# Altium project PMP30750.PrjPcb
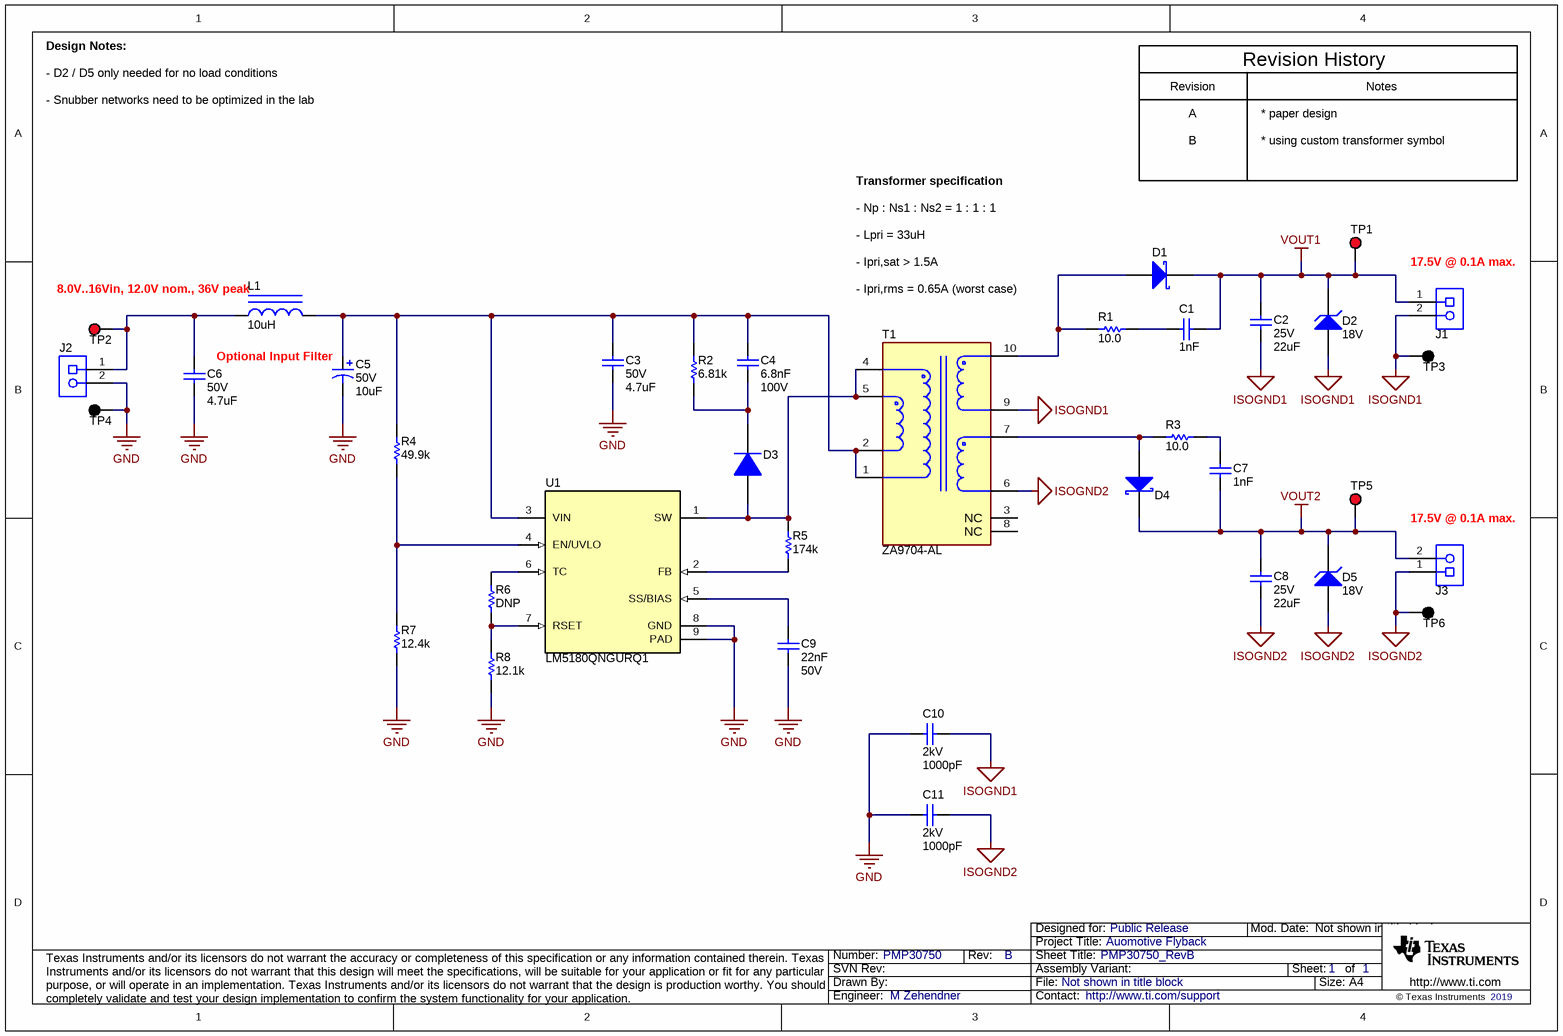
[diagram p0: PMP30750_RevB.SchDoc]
CopyrightYear: 2019; PCB_Rev: A; PRJ_Customer: Public Release; PRJ_Engineer: M Zehendner; PRJ_Number: PMP30750; PRJ_Title: Auomotive Flyback; SCH_Rev: B; TechSupport: http://www.ti.com/support; TID: N/A
1 sheet, 36 parts. Net scope: global (net labels, ports and power ports of the same name join across sheets).
Board file: PMP30750.PcbDoc

## Sheet PMP30750_RevB.SchDoc: PMP30750_RevB
size A4; Date: Not shown in title block; ApprovedBy: Not shown in title block; CheckedBy: Not shown in title block; Author: Not shown in title block; CompanyName: Not shown in title block; Engineer: Not shown in title block; Organization: Not shown in title block; Address1: Not shown in title block; Address2: Not shown in title block; Address3: Not shown in title block; Address4: Not shown in title block; DocumentNumber: 1; Revision: Use project parameter SCH_Rev; SheetNumber: 1; SheetTotal: 1; PageSetup: Record=PageOptions¦CenterHorizontal=True¦CenterVertical=True¦PrintScale=0.70¦XCorrection=1.00¦YCorrection=1.00¦PrintKind=0¦BorderSize=5000000¦LeftOffset=0¦BottomOffset=0¦Orientation=2¦PaperLength=1000¦PaperWidth=1000¦Scale=100¦PaperSource=15¦PrintQuality=600¦MediaType=1¦DitherType=10¦PaperKind=A4¦PrintScaleMode=1

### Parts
C1  Cap_F: 1nF  [0603]  (hidden comment: GRM188R71H102KA01D)
C2  VDC_V: 25V  ValueDisplayed: 22uF  [1210_270]  (hidden comment: TMK325B7226MM-PR)
C3  VDC_V: 50V  ValueDisplayed: 4.7uF  [1206_180]  (hidden comment: GRM31CR71H475KA12L)
C4  Cap_F: 6.8nF  VDC_V: 100V  [0603]  (hidden comment: GRM188R72A682KA01D)
C5  VDC_V: 50V  ValueDisplayed: 10uF  [SM_RADIAL_D]  (hidden comment: EEE-FK1H100P)
C6  VDC_V: 50V  ValueDisplayed: 4.7uF  [1206_180]  (hidden comment: GRM31CR71H475KA12L)
C7  Cap_F: 1nF  [0603]  (hidden comment: GRM188R71H102KA01D)
C8  VDC_V: 25V  ValueDisplayed: 22uF  [1210_270]  (hidden comment: TMK325B7226MM-PR)
C9  Cap_F: 22nF  VDC_V: 50V  [0603]  (hidden comment: GRM188R71H223KA01D)
C10  VDC_V: 2kV  ValueDisplayed: 1000pF  [1206_180]  (hidden comment: C1206C102KGRACAUTO)
C11  VDC_V: 2kV  ValueDisplayed: 1000pF  [1206_180]  (hidden comment: C1206C102KGRACAUTO)
D1  PMEG6010CEH,115  [SOD-123F]  (value not drawn)
D2  value 18V  [SOD-123]  (hidden comment: MMSZ5248B-7-F)
D3  BAS16D-E3-08  [SOD-123]  (value not drawn)
D4  PMEG6010CEH,115  [SOD-123F]  (value not drawn)
D5  value 18V  [SOD-123]  (hidden comment: MMSZ5248B-7-F)
J1  ED120/2DS  [On-Shore_ED120_2DS]  (value not drawn)
J2  ED120/2DS  [On-Shore_ED120_2DS]  (value not drawn)
J3  ED120/2DS  [On-Shore_ED120_2DS]  (value not drawn)
L1  ValueDisplayed: 10uH  [IHLP-2525CZ]  (hidden comment: IHLP2525CZER100M5A)
R1  ValueDisplayed: 10.0  [0603]  (hidden comment: CRCW060310R0FKEAHP)
R2  ValueDisplayed: 6.81k  [0603]  (hidden comment: CRCW06036K81FKEA)
R3  ValueDisplayed: 10.0  [0603]  (hidden comment: CRCW060310R0FKEAHP)
R4  ValueDisplayed: 49.9k  [0603]  (hidden comment: CRCW060349K9FKEA)
R5  ValueDisplayed: 174k  [0603]  (hidden comment: CRCW0603174KFKEA)
R6  ValueDisplayed: DNP  [0603]  (hidden comment: CRCW0603432KFKEA)
R7  ValueDisplayed: 12.4k  [0603]  (hidden comment: CRCW060312K4FKEA)
R8  ValueDisplayed: 12.1k  [0603]  (hidden comment: CRCW060312K1FKEA)
T1  ZA9704-AL  [FP-ZA9704-AL_SMD10-MFG]
TP1  5010  [Keystone5010]  (value not drawn)
TP2  5010  [Keystone5010]  (value not drawn)
TP3  5011  [Keystone5011]  (value not drawn)
TP4  5011  [Keystone5011]  (value not drawn)
TP5  5010  [Keystone5010]  (value not drawn)
TP6  5011  [Keystone5011]  (value not drawn)
U1  LM5180QNGURQ1  [NGU0008C]

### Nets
GND: C3.2 C5.2(-) C6.2 C9.2 C10.2 C11.2 J2.2 R7.1 R8.1 TP4.1 U1.8(GND) U1.9(PAD)
ISOGND1: C2.2 C10.1 D2.2(A) J1.2 T1.9 TP3.1
ISOGND2: C8.2 C11.1 D5.2(A) J3.1 T1.6 TP6.1
VOUT1: C1.1 C2.1 D1.1(K) D2.1(K) J1.1 TP1.1
VOUT2: C7.2 C8.1 D4.1(K) D5.1(K) J3.2 TP5.1
NetC1_2: C1.2 R1.2
NetC3_1: C3.1 C4.1 C5.1(+) L1.2 R2.2 R4.2 T1.1 T1.2 U1.3(VIN)
NetC4_2: C4.2 D3.1(K) R2.1
NetC6_1: C6.1 J2.1 L1.1 TP2.1
NetC7_1: C7.1 R3.2
NetC9_1: C9.1 U1.5(SS/BIAS)
NetD1_2: D1.2(A) R1.1 T1.10
NetD3_2: D3.2(A) R5.2 T1.4 T1.5 U1.1(SW)
NetD4_2: D4.2(A) R3.1 T1.7
NetR4_1: R4.1 R7.2 U1.4(EN/UVLO)
NetR5_1: R5.1 U1.2(FB)
NetR6_1: R6.1 R8.2 U1.7(RSET)
NetR6_2: R6.2 U1.6(TC)

Not connected (* = marked no-connect by the designer): T1 3(NC) 8(NC)

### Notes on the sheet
- Design Notes:
- - D2 / D5 only needed for no load conditions
- - Snubber networks need to be optimized in the lab
- Revision
- A
- * paper design
- Revision History
- Notes
- Transformer specification
- B
- * using custom transformer symbol
- - Np : Ns1 : Ns2 = 1 : 1 : 1
- - Lpri = 33uH
- 8.0V..16Vin, 12.0V nom., 36V peak
- - Ipri,sat > 1.5A
- - Ipri,rms = 0.65A (worst case)
- (near J1) 17.5V @ 0.1A max.
- (near C5) Optional Input Filter
- (near J3) 17.5V @ 0.1A max.

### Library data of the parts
C1 C7 = CMP-0007432-5: CAP, CERM, 1000 pF, 50 V, +/- 10%, X7R, 0603; Manufacturer: MuRata; TaMin_C: -55°C; Polarized: N; SizeAreaWB_mm2: 4.68; Value1: Unknown; U/M: EA; Value: 1000pF; TaMax_C: 125°C; SizeZ_mm: 1; SizeX_mm: 1.6; SizeY_mm: 0.8; Value2: 50V; SizeArea_mm2: 1.28; AEC Category: Q200
C2 C8 = CMP-0009255-2: CAP, CERM, 22 uF, 25 V, +/- 10%, X7R, AEC-Q200 Grade 1, 1210; Manufacturer: Taiyo Yuden; TaMin_C: -55°C; Polarized: N; SizeAreaWB_mm2: 14.7; Value1: Unknown; U/M: EA; Value: 22uF; TaMax_C: 125°C; SizeZ_mm: 2.7; SizeX_mm: 3.2; SizeY_mm: 2.5; Cap_Case: 1210; SizeArea_mm2: 8; AEC Qualified: Y; Cap_F: 22µF; AEC Grade: 1; AEC Category: Q200
C3 C6 = CMP-0008969-2: CAP, CERM, 4.7 uF, 50 V, +/- 10%, X7R, 1206; Manufacturer: MuRata; TaMin_C: -55°C; Polarized: N; SizeAreaWB_mm2: 10.92; Value1: Unknown; U/M: EA; Value: 4.7uF; TaMax_C: 125°C; SizeZ_mm: 1.8; SizeX_mm: 3.2; SizeY_mm: 1.6; Cap_Case: 2220; SizeArea_mm2: 5.12; Cap_F: 4.7µF; AEC Category: Q200
C4 = CMP-0007487-4: CAP, CERM, 6800 pF, 100 V, +/- 10%, X7R, 0603; Manufacturer: MuRata; TaMin_C: -55°C; Polarized: N; SizeAreaWB_mm2: 4.68; Value1: Unknown; U/M: EA; Value: 6800pF; TaMax_C: 125°C; SizeZ_mm: 1; SizeX_mm: 1.6; SizeY_mm: 0.8; SizeArea_mm2: 1.28; AEC Category: Q200
C5 = CMP-0011175-2: CAP, AL, 10 uF, 50 V, +/- 20%, 0.88 ohm, AEC-Q200 Grade 2, SMD; Manufacturer: Panasonic; TaMin_C: -55°C; ESR_ohm: 0.88; Polarized: Y; SizeAreaWB_mm2: 84.28; U/M: EA; Value: 10uF; TaMax_C: 105°C; SizeZ_mm: 5.4; SizeX_mm: 7.8; SizeY_mm: 6.6; Cap_Case: D; SizeArea_mm2: 51.48; CompType: Capacitor; Cap_F: 10µF; IRMS_A: 165mA; AEC Grade: 2; AEC Category: Q200
C9 = CMP-0007444-4: CAP, CERM, 0.022 uF, 50 V, +/- 10%, X7R, 0603; Manufacturer: MuRata; TaMin_C: -55°C; Polarized: N; SizeAreaWB_mm2: 4.68; Value1: Unknown; U/M: EA; TaMax_C: 125°C; SizeZ_mm: 1; SizeX_mm: 1.6; SizeY_mm: 0.8; SizeArea_mm2: 1.28; AEC Category: Q200
C10 C11 = CMP-0008579-2: CAP, CERM, 1000 pF, 2000 V, +/- 10%, X7R, AEC-Q200 Grade 1, 1206; Manufacturer: Kemet; TaMin_C: -55°C; Polarized: N; SizeAreaWB_mm2: 10.92; Value1: Unknown; U/M: EA; Value: 1000pF; TaMax_C: 125°C; SizeZ_mm: 1.8; SizeX_mm: 3.2; SizeY_mm: 1.6; Cap_Case: 1206; Value2: 2000V; SizeArea_mm2: 5.12; AEC Qualified: Y; Cap_F: 1nF; AEC Grade: 1; AEC Category: Q200
D1 D4 = CMP-0028377-2: Diode, Schottky, 60 V, 1 A, SOD-123F; Manufacturer: Nexperia; Value1: 1A; Value2: 0.57V; TJmax_C: 150°C; Green_REACh: Incomplete; Vr_V: 60V; SizeY_mm: 1.6; Vf_V: 570mV; SizeArea_mm2: 5.6; AEC Category: Q101; SizeZ_mm: 1.1; SizeX_mm: 3.5; Value: 60V; Green_Lifecycle: Not Set; SizeAreaWB_mm2: 11.7
D2 D5 = CMP-0005755-1: Diode, Zener, 18 V, 500 mW, SOD-123; Manufacturer: Diodes Inc.; Power_W: 500mW; SizeAreaWB_mm2: 13.095; Value1: 0.5W; RJA_CperW: 350; U/M: EA; SizeZ_mm: 1.35; SizeX_mm: 3.85; SizeY_mm: 1.7; SizeArea_mm2: 6.545; AEC Category: Q101
D3 = CMP-0080761-1: Diode, Switching, 100 V, 0.25 A, AEC-Q101, SOD-123; Manufacturer: Vishay-Semiconductor; Io_A: 250mA; SizeAreaWB_mm2: 13.095; Vr_V: 100V; Value1: 0.25A; TJmax_C: 150°C; Value: 100V; SizeZ_mm: 1.35; SizeX_mm: 3.85; SizeY_mm: 1.7; Vf_V: 1.25V; SizeArea_mm2: 6.545; AEC Qualified: Y; AEC Category: Q101
J1-J3 = CMP-0074910-1: Terminal Block, 5.08 mm, 2x1, Brass, TH; Manufacturer: On-Shore Technology; Cert_VDE: Y; CNHeader: False; Current_A: 15A; Green_Lifecycle: Not Set; Shrouded: N; Gender: Female; Green_REACh: Incomplete; Voltage_V: 300V; Row_Count: 1; Pitch_mm: 5.08; CT: True
L1 = CMP-0063375-1: Inductor, Shielded, 10 uH, 2.9 A, 0.0719 ohm, SMD; Manufacturer: Vishay-Dale; Isat: 2.9A @ 20% inductance drop; Irms: 4A @ 40C rise; Green_Lifecycle: Active; SizeAreaWB_mm2: 75.0442; DCR_ohm: 0.0719; Green_REACh: Passed; Value: 10uH; Imax_A: 2.9A; SizeZ_mm: 3; SizeX_mm: 6.86; SizeY_mm: 6.47; SizeArea_mm2: 44.3842; Ind_H: 10µH; AEC Category: Q200
R1 R3 = CMP-0022004-4: RES, 10.0, 1%, 0.25 W, AEC-Q200 Grade 0, 0603; Manufacturer: Vishay-Dale; Power_W: 250mW; TempCo: 100 ppm/C; Value_Code: 10R0; Value: 10.0; EIA_Code: E96; Res_ohm: 10; SizeX_mm: 1.6; SizeY_mm: 0.8; SizeZ_mm: 1; Value2: 0.25W; SizeArea_mm2: 1.28; AEC Qualified: Y; VDC_V: 75V; AEC Category: Q200; AEC Grade: 0
R2 = CMP-0022563-4: RES, 6.81 k, 1%, 0.1 W, AEC-Q200 Grade 0, 0603; Manufacturer: Vishay-Dale; Power_W: 100mW; TempCo: 100 ppm/C; Value_Code: 6k81; Value: 6.81k; EIA_Code: E96; SizeX_mm: 1.6; SizeY_mm: 0.8; SizeZ_mm: 1; Value2: 0.1W; SizeArea_mm2: 1.28; AEC Qualified: Y; VDC_V: 75V; AEC Category: Q200; AEC Grade: 0
R4 = CMP-0022447-4: RES, 49.9 k, 1%, 0.1 W, AEC-Q200 Grade 0, 0603; Manufacturer: Vishay-Dale; Power_W: 100mW; TempCo: 100 ppm/C; Value_Code: 49k9; Value: 49.9k; EIA_Code: E96; SizeX_mm: 1.6; SizeY_mm: 0.8; SizeZ_mm: 1; Value2: 0.1W; SizeArea_mm2: 1.28; AEC Qualified: Y; VDC_V: 75V; AEC Category: Q200; AEC Grade: 0
R5 = CMP-0022085-4: RES, 174 k, 1%, 0.1 W, AEC-Q200 Grade 0, 0603; Manufacturer: Vishay-Dale; Power_W: 100mW; TempCo: 100 ppm/C; Value: 174k; EIA_Code: E96; SizeX_mm: 1.6; SizeY_mm: 0.8; SizeZ_mm: 1; Value2: 0.1W; SizeArea_mm2: 1.28; AEC Qualified: Y; VDC_V: 75V; AEC Category: Q200; AEC Grade: 0
R6 = CMP-0022420-4: RES, 432 k, 1%, 0.1 W, AEC-Q200 Grade 0, 0603; Manufacturer: Vishay-Dale; Power_W: 100mW; TempCo: 100 ppm/C; Value_Code: 432k; Value: 432k; EIA_Code: E96; SizeX_mm: 1.6; SizeY_mm: 0.8; SizeZ_mm: 1; Value2: 0.1W; SizeArea_mm2: 1.28; AEC Qualified: Y; VDC_V: 75V; AEC Category: Q200; AEC Grade: 0
R7 = CMP-0022031-4: RES, 12.4 k, 1%, 0.1 W, AEC-Q200 Grade 0, 0603; Manufacturer: Vishay-Dale; Power_W: 100mW; TempCo: 100 ppm/C; Value_Code: 12k4; Value: 12.4k; EIA_Code: E96; SizeX_mm: 1.6; SizeY_mm: 0.8; SizeZ_mm: 1; Value2: 0.1W; SizeArea_mm2: 1.28; AEC Qualified: Y; VDC_V: 75V; AEC Category: Q200; AEC Grade: 0
R8 = CMP-0022030-4: RES, 12.1 k, 1%, 0.1 W, AEC-Q200 Grade 0, 0603; Manufacturer: Vishay-Dale; Power_W: 100mW; TempCo: 100 ppm/C; Value_Code: 12k1; Value: 12.1k; EIA_Code: E96; SizeX_mm: 1.6; SizeY_mm: 0.8; SizeZ_mm: 1; Value2: 0.1W; SizeArea_mm2: 1.28; AEC Qualified: Y; VDC_V: 75V; AEC Category: Q200; AEC Grade: 0
T1 = CMP-0086949-1: FLYBACK TRANSFORMER; Manufacturer: Coilcraft; SizeZ_mm: 6.5mm; Ind_H: 32µH; Ns1toNp: 1:1:1; AEC Qualified: No
TP1 TP2 TP5 = CMP-0055147-1: Test Point, Multipurpose, Red, TH; Manufacturer: Keystone; CNHeader: FALSE; Green_Lifecycle: Active; Green_REACh: Passed; ContactFinish: Silver; CT: TRUE
TP3 TP4 TP6 = CMP-0055148-1: Test Point, Multipurpose, Black, TH; Manufacturer: Keystone; CNHeader: FALSE; Green_Lifecycle: Active; Green_REACh: Passed; ContactFinish: Silver; CT: TRUE
U1 = CMP-0078633-2: 70-V PSR Flyback Converter With 100-V, 1.2-A Power Switch and Ultra-Low IQ, NGU0008C (WSON-8); Alternate PartNumber: LM5180QNGUTQ1; Alternate Manufacturer: Texas Instruments; SizeAreaWB_mm2: 25; SizeZ_mm: 0.8; SizeX_mm: 4; SizeArea_mm2: 16; CompType: IC; AEC Qualified: Y; AEC Category: Q200

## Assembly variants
001: not fitted FID1 FID2 FID3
